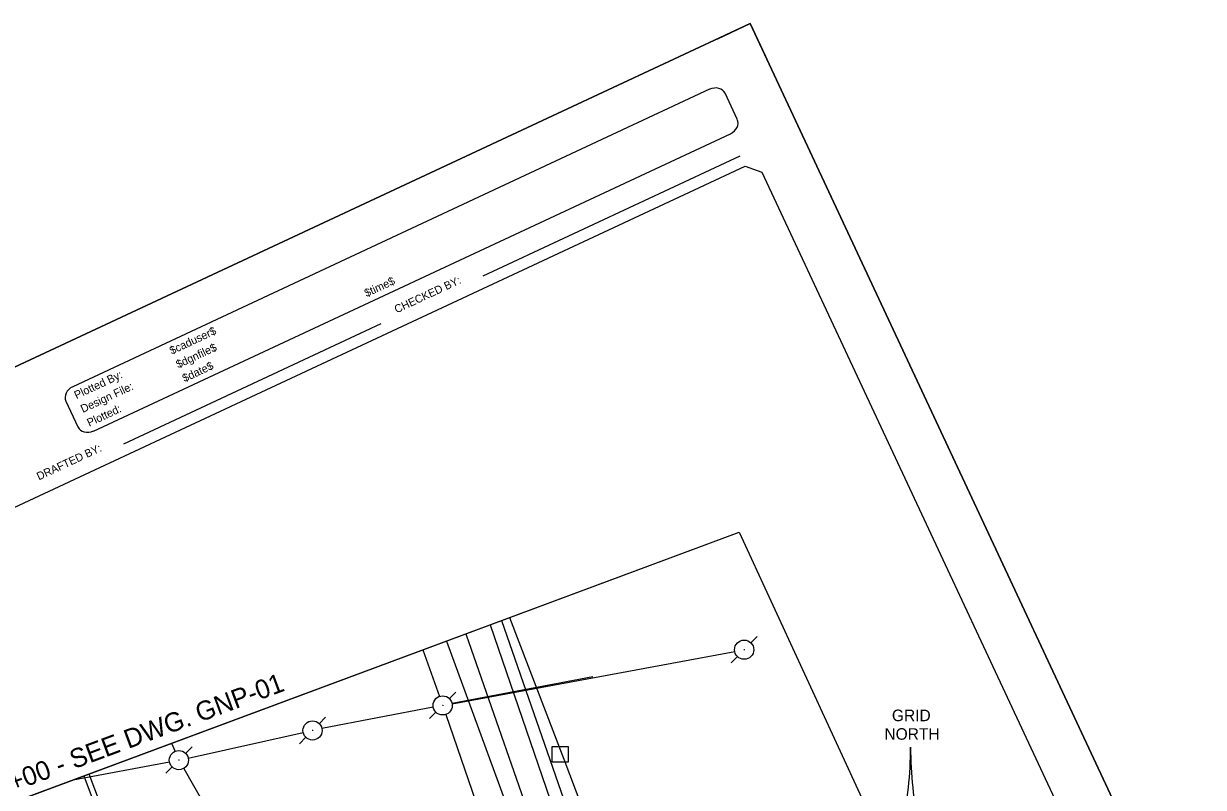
# Model space of a CAD drawing. Extents: x 1040364 to 1041050, y 1127298 to 1128100.
# Drawn here: x 1040619.4 to 1040851.7, y 1127949.4 to 1128099.9 of the extents above; entities that cross this region are included whole.
import ezdxf

# ---------------------------------------------------------------- set-up
doc = ezdxf.new("R2010")
doc.units = 0
for name, color, linetype in [('clip boundary', 7, 'Continuous'), ('DELB', 7, 'Continuous'), ('MHB', 7, 'Continuous'), ('MPM', 7, 'Continuous'), ('NBS_P', 7, 'Continuous'), ('NBS_P_T', 7, 'Continuous'), ('NML_P', 7, 'Continuous'), ('NML_P_T', 7, 'Continuous'), ('NNA_P', 7, 'Continuous'), ('PE', 7, 'Continuous'), ('SHEET_BORDER', 7, 'Continuous'), ('SHEET_BORDER_CUT', 7, 'Continuous'), ('SHEET_BORDER_TEXT', 7, 'Continuous'), ('STSEW', 7, 'Continuous'), ('UEO', 7, 'Continuous'), ('UP', 7, 'Continuous'), ('UPGW', 7, 'Continuous')]:
    doc.layers.add(name, color=color, linetype=linetype)

msp = doc.modelspace()

# ---------------------------------------------------------------- linework, layer by layer
at = {"layer": 'clip boundary'}
for points in [[(1040762.51, 1128099.9), (1041050.31, 1127483.8), (1040651.66, 1127297.58), (1040363.86, 1127913.67)], [(1040504.79, 1127904.67), (1040760.34, 1127999.71), (1040984.84, 1127512.73), (1040710.81, 1127382.18)]]:
    msp.add_lwpolyline(points, close=True, dxfattribs=at)
at = {"layer": 'DELB'}
for points in [[(1040711.25, 1127981.45), (1040725.46, 1127940.06), (1040746.27, 1127894.3), (1040764.19, 1127846.72)], [(1040713.54, 1127982.3), (1040727.79, 1127941.15), (1040748.7, 1127895.13), (1040765.65, 1127847.45)], [(1040757.16, 1127846.54), (1040740.28, 1127889.15), (1040718.94, 1127933.92), (1040702.72, 1127978.14), (1040702.66, 1127978.26)], [(1040759.55, 1127847.27), (1040743.47, 1127890.1), (1040721.93, 1127935.56), (1040706.63, 1127979.42), (1040706.5, 1127979.69)]]:
    msp.add_lwpolyline(points, dxfattribs=at)
at = {"layer": 'MHB'}
msp.add_lwpolyline([(1040715.1, 1127982.88), (1040725.76, 1127955.01), (1040791.8, 1127780.06), (1040839.44, 1127671.87), (1040933.95, 1127556.77), (1040967.39, 1127504.42)], dxfattribs=at)
at = {"layer": 'MPM'}
for p, q in [((1040723.49, 1127954.4), (1040723.49, 1127957.47)), ((1040723.49, 1127957.47), (1040726.65, 1127957.47)), ((1040726.65, 1127957.47), (1040726.65, 1127954.4)), ((1040726.65, 1127954.4), (1040723.49, 1127954.4))]:
    msp.add_line(p, q, dxfattribs=at)
at = {"layer": 'NBS_P'}
for p, q in [((1040754.5, 1128086.96), (1040629.07, 1128028.36)), ((1040759.94, 1128081.04), (1040757.54, 1128086.17)), ((1040633.16, 1128019.6), (1040758.59, 1128078.2)), ((1040627.7, 1128025.52), (1040630.08, 1128020.43))]:
    msp.add_line(p, q, dxfattribs=at)
for centre, major_axis, start_param, end_param in [((1040755.35, 1128085.14), (2.19, 1.02), 0, 1.570796), ((1040757.75, 1128080.01), (2.19, 1.02), 4.712389, 6.283185), ((1040629.91, 1128026.55), (-2.19, -1.02), 4.712389, 6.283185), ((1040632.29, 1128021.46), (-2.19, -1.02), 0, 1.570796)]:
    msp.add_ellipse(centre, major_axis=major_axis, ratio=0.825959, start_param=start_param, end_param=end_param, dxfattribs=at)
at = {"layer": 'NML_P'}
msp.add_line((1040504.79, 1127904.67), (1040760.34, 1127999.71), dxfattribs=at)
at = {"layer": 'NNA_P'}
for centre, start, end in [((1040720.98, 1127957.19), 347.6515, 0.1139), ((1040867.16, 1127957.19), 179.8844, 192.3468)]:
    msp.add_arc(centre, 73.09, start, end, dxfattribs=at)
at = {"layer": 'PE'}
msp.add_lwpolyline([(1040632.25, 1127952.07), (1040649.62, 1127906.04), (1040655.5, 1127890.52), (1040667.36, 1127859.52), (1040679.42, 1127828.44), (1040685.53, 1127812.93), (1040691.68, 1127797.52), (1040704.12, 1127766.75), (1040723.07, 1127720.54), (1040735.94, 1127689.83), (1040742.48, 1127674.51), (1040755.79, 1127643.96), (1040762.56, 1127628.73), (1040769.44, 1127613.48), (1040783.38, 1127583.06), (1040797.39, 1127552.96), (1040804.47, 1127537.94), (1040826.05, 1127492.6), (1040847.29, 1127447.58), (1040847.43, 1127447.27)], dxfattribs=at)
at = {"layer": 'SHEET_BORDER'}
for p, q in [((1040709.88, 1128050.18), (1040760.54, 1128073.84)), ((1040639.16, 1128017.14), (1040689.82, 1128040.81))]:
    msp.add_line(p, q, dxfattribs=at)
msp.add_lwpolyline([(1040652.69, 1127325.65), (1040649.37, 1127326.86), (1040384.85, 1127893.12), (1040386.05, 1127896.45), (1040761.49, 1128071.82), (1040764.81, 1128070.62), (1041029.33, 1127504.35), (1041028.12, 1127501.03)], close=True, dxfattribs=at)
at = {"layer": 'SHEET_BORDER_CUT'}
msp.add_lwpolyline([(1040363.86, 1127913.67), (1040651.66, 1127297.58), (1041050.31, 1127483.8), (1040762.51, 1128099.9)], close=True, dxfattribs=at)
msp.add_lwpolyline([(1040756.11, 1128096.9), (1040762.51, 1128099.9), (1040765.51, 1128093.49)], dxfattribs=at)
at = {"layer": 'STSEW'}
msp.add_lwpolyline([(1040631.23, 1127951.69), (1040648.51, 1127905.59), (1040654.39, 1127890.06), (1040666.38, 1127859.09), (1040684.56, 1127812.57), (1040690.71, 1127797.15), (1040703.13, 1127766.35), (1040715.7, 1127735.48), (1040722.06, 1127720.07), (1040728.5, 1127704.72), (1040741.59, 1127674.11), (1040754.93, 1127643.58), (1040761.69, 1127628.35), (1040768.56, 1127613.09), (1040782.51, 1127582.66), (1040803.66, 1127537.47), (1040825.13, 1127492.13), (1040846.44, 1127447.18), (1040846.59, 1127446.87)], dxfattribs=at)
at = {"layer": 'UEO'}
for points in [[(1040703.79, 1127965.92), (1040759.44, 1127976.2)], [(1040700.07, 1127965.22), (1040678.16, 1127961)], [(1040702.54, 1127963.79), (1040719.62, 1127914.05)], [(1040651.83, 1127955.21), (1040674.46, 1127960.23)], [(1040629.18, 1127950.93), (1040648.12, 1127954.45)], [(1040650.92, 1127953.15), (1040683.17, 1127896.49)]]:
    msp.add_lwpolyline(points, dxfattribs=at)
at = {"layer": 'UP'}
for p, q in [((1040762.63, 1127977.89), (1040763.88, 1127979.14)), ((1040761.36, 1127976.55), (1040761.24, 1127976.55)), ((1040761.3, 1127976.61), (1040761.3, 1127976.48)), ((1040759.97, 1127975.21), (1040758.72, 1127973.95)), ((1040703.26, 1127966.92), (1040704.51, 1127968.18)), ((1040700.59, 1127964.24), (1040699.34, 1127962.98)), ((1040701.99, 1127965.58), (1040701.86, 1127965.58)), ((1040701.93, 1127965.64), (1040701.93, 1127965.51)), ((1040677.63, 1127961.98), (1040678.88, 1127963.24)), ((1040676.36, 1127960.64), (1040676.24, 1127960.64)), ((1040676.3, 1127960.7), (1040676.3, 1127960.58)), ((1040651.32, 1127956.14), (1040652.56, 1127957.39)), ((1040674.97, 1127959.3), (1040673.72, 1127958.04)), ((1040650.05, 1127954.8), (1040649.92, 1127954.8)), ((1040649.98, 1127954.86), (1040649.98, 1127954.73)), ((1040648.65, 1127953.45), (1040647.4, 1127952.2))]:
    msp.add_line(p, q, dxfattribs=at)
for centre in [(1040761.3, 1127976.55), (1040701.93, 1127965.58), (1040676.3, 1127960.64), (1040649.98, 1127954.8)]:
    msp.add_circle(centre, 1.89, dxfattribs=at)
at = {"layer": 'UPGW'}
for points in [[(1040698.04, 1127976.54), (1040701.29, 1127967.36)], [(1040731.53, 1127971.22), (1040703.78, 1127965.93)], [(1040648.51, 1127958.12), (1040649.22, 1127956.53)]]:
    msp.add_lwpolyline(points, dxfattribs=at)

# ---------------------------------------------------------------- texts
at = {"layer": 'NBS_P_T'}
for s, height, p in [('$time$', 1.576, (1040686.96, 1128045.98)), ('$caduser$', 1.576, (1040648.58, 1128034.66)), ('$dgnfile$', 1.576, (1040649.85, 1128031.95)), ('$date$', 1.576, (1040651.11, 1128029.23)), ('Plotted By:', 1.5759, (1040629.8, 1128025.89)), ('Design File:', 1.5759, (1040631.07, 1128023.18)), ('Plotted:', 1.576, (1040632.33, 1128020.46))]:
    msp.add_text(s, height=height, rotation=25.0392, dxfattribs=at).set_placement(p)
at = {"layer": 'NML_P_T'}
msp.add_text('MATCHLINE STA. 2+00 - SEE DWG. GNP-01', height=3.744, rotation=20.4011, dxfattribs=at).set_placement((1040574.42, 1127932.6))
at = {"layer": 'NNA_P'}
for s, p in [('GRID', (1040790.4, 1127962.47)), ('NORTH', (1040788.93, 1127958.81))]:
    msp.add_text(s, height=2.283, rotation=359.9991, dxfattribs=at).set_placement(p)
at = {"layer": 'SHEET_BORDER_TEXT'}
for s, p in [('CHECKED BY:', (1040692.86, 1128042.8)), ('DRAFTED BY:', (1040622.41, 1128009.89))]:
    msp.add_text(s, height=1.5625, rotation=25.0387, dxfattribs=at).set_placement(p)

doc.saveas('drawing.dxf')
